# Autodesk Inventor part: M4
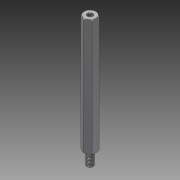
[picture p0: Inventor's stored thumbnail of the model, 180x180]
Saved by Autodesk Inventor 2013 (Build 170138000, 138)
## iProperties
Created: 2012-08
Part Number: M4
Material: Stahl
Document SubType Name: Modeling
Designer: rYan
Density: 7.85 g/cm^3
Author: rYan
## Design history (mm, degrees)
derived "Abstandsbolzen Typ B.ipt"
feature "Volumenkörper1::Abstandsbolzen Typ B.ipt"
tag "Bezeichnung1"
node "Volumenkörper1"
other parameters: "SW" = 7, "d2" = 0, "l_" = 9, "d9" = 118 deg, "GA_" = 4, "A_" = 8, "d13" = 0, "d17" = 0.25, "d20" = 45 deg
